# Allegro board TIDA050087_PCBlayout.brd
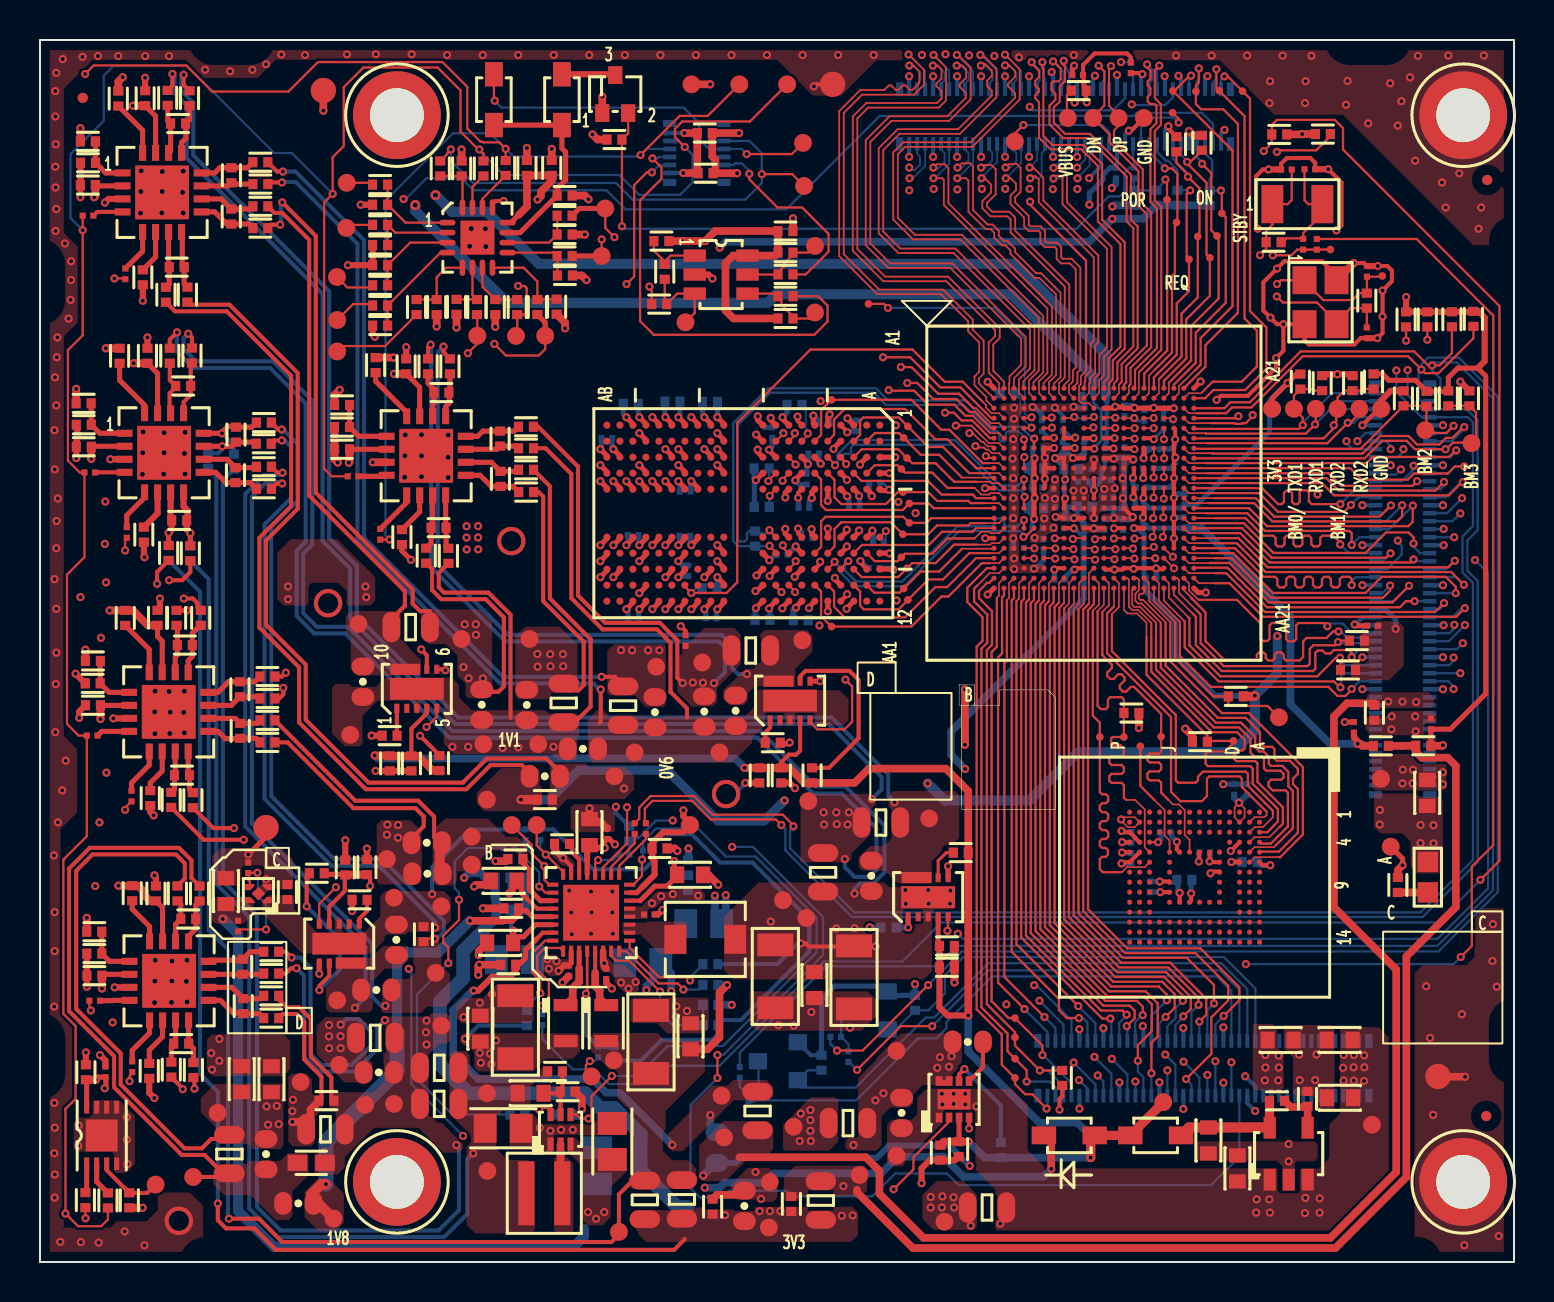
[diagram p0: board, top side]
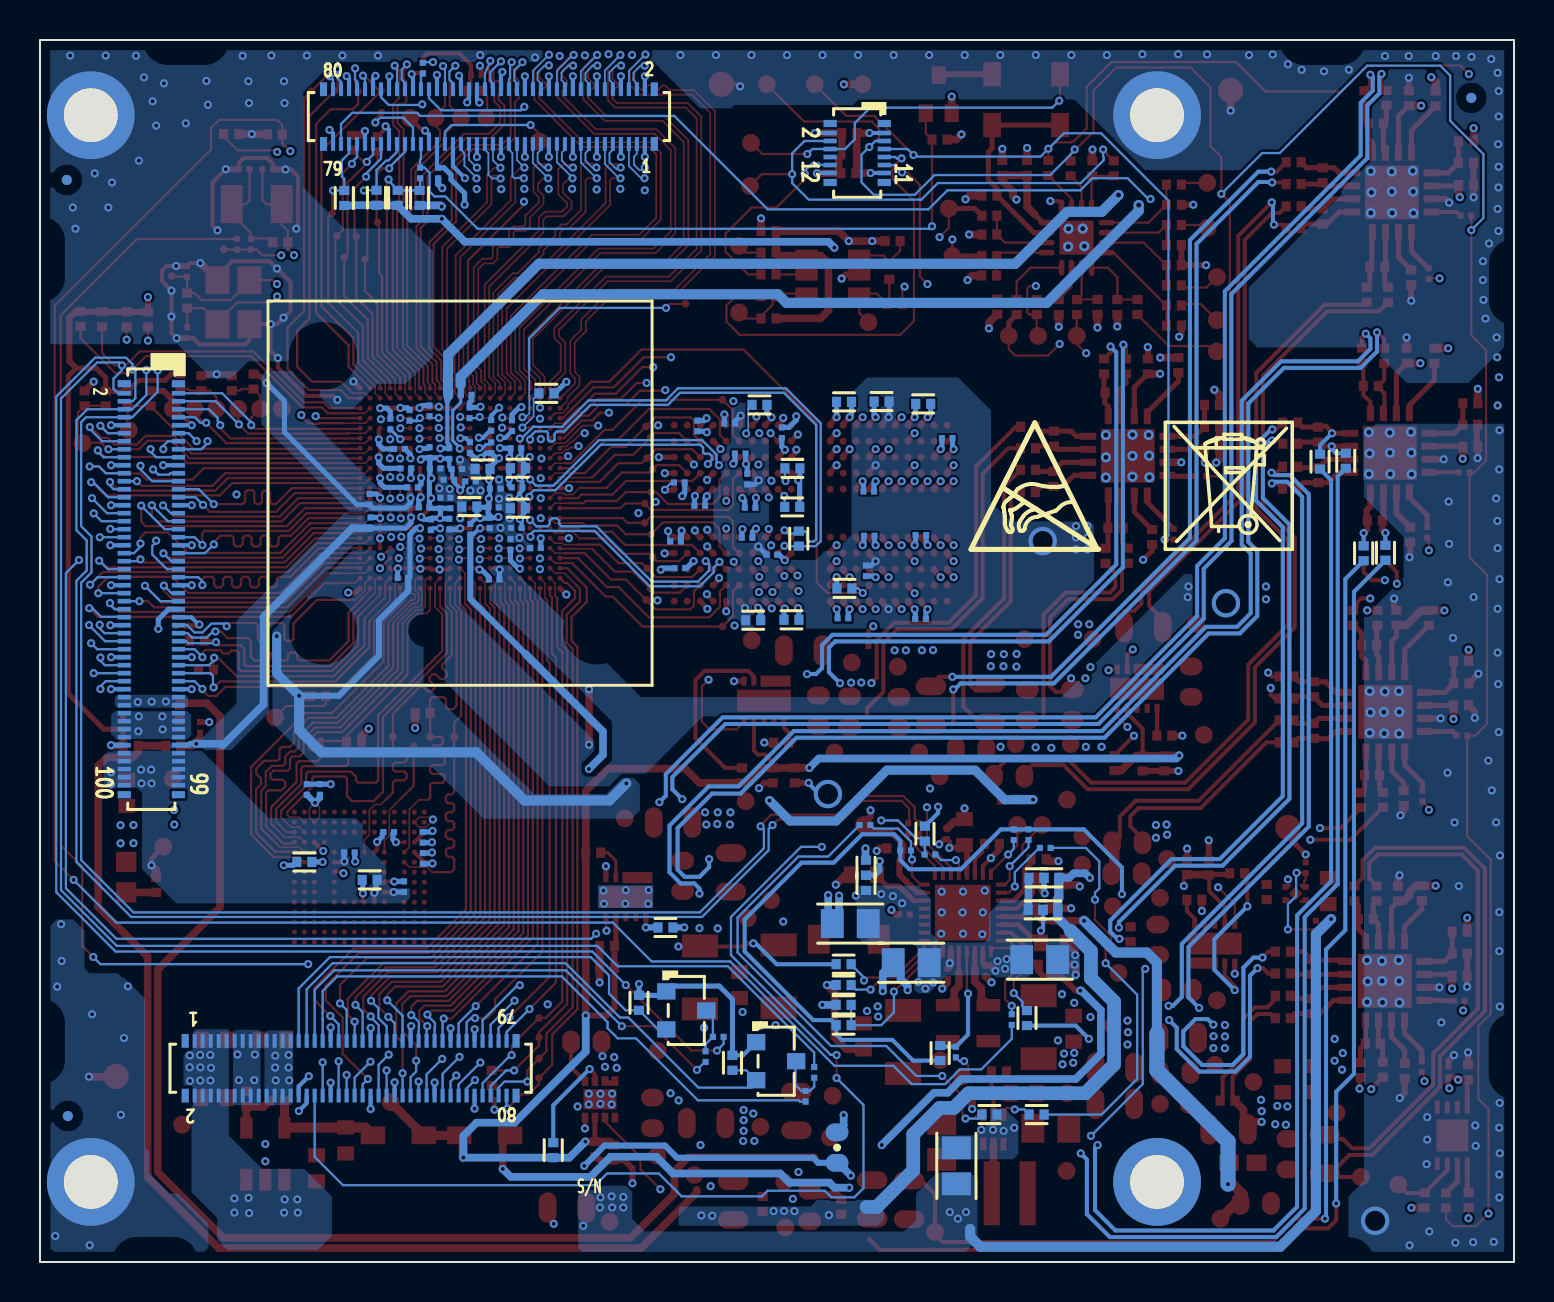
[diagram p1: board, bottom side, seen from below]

Outline 73.74 x 61.11 mm; copper layers: TOP, L2_GND_1, L3_INT_1, L4_PWR, L5_GND_2, BOTTOM. Coordinates in mm from the lower left corner of the outline.
Outline path: rectangle 0,0 73.74,61.11

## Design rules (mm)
constraint set DEFAULT: min track width 0.112, pair gap 0.127
net group DP1: nets I2C2_SCL I2C2_SDA
net group @SCH-51943_B2_0411A.MCIMX93-SOM: nets ADC_IN0 ADC_IN1 ADC_IN2 ADC_IN3 CLKIN1 CLKIN2 CLKO01 CLKO02 CLKO03 CLKO04 CSI_CLK_N CSI_CLK_P CSI_D0_N CSI_D0_P CSI_D1_N CSI_D1_P DRAM_CA0_A DRAM_CA1_A DRAM_CA2_A DRAM_CA3_A DRAM_CA4_A DRAM_CA5_A DRAM_CK_C_A DRAM_CK_T_A DRAM_CKE0_A DRAM_CKE1_A DRAM_DATA0_A DRAM_DATA1_A DRAM_DATA2_A DRAM_DATA3_A DRAM_DATA4_A DRAM_DATA5_A DRAM_DATA6_A DRAM_DATA7_A DRAM_DATA8_A DRAM_DATA9_A DRAM_DATA10_A DRAM_DATA11_A DRAM_DATA12_A DRAM_DATA13_A DRAM_DATA14_A DRAM_DATA15_A DRAM_DMI0_A DRAM_DMI1_A DRAM_NCS0_A DRAM_NCS1_A DRAM_NRESET DRAM_SDQS0_C_A DRAM_SDQS0_T_A DRAM_SDQS1_C_A DRAM_SDQS1_T_A DRAM_ZN DRAM_ZQ0 DSI_CLK_N DSI_CLK_P DSI_D0_N DSI_D0_P DSI_D1_N DSI_D1_P DSI_D2_N DSI_D2_P DSI_D3_N DSI_D3_P EMMC_VDDIM ENET1_MDC ENET1_MDIO ENET1_RD0 ENET1_RD1 ENET1_RD2 ENET1_RD3 ENET1_RX_CTL ENET1_RXC ENET1_TD0 ENET1_TD1 ENET1_TD2 ENET1_TD3 ENET1_TX_CTL ENET1_TXC ENET2_MDC ENET2_MDIO ENET2_RD0 ENET2_RD1 ENET2_RD2 ENET2_RD3 ENET2_RX_CTL ENET2_RXC ENET2_TD0 ENET2_TD1 ENET2_TD2 ENET2_TD3 ENET2_TX_CTL ENET2_TXC FSC_CTRL_H1 FSC_CTRL_H2 FSC_CTRL_H3 FSC_CTRL_H4 FSC_CTRL_H5 FSC_CTRL_L1 FSC_CTRL_L2 FSC_CTRL_L3 FSC_CTRL_L4 FSC_CTRL_L5 FT_EECLK FT_EECS FT_EEDATA FT_IO_NINT FT_IO_NRST FT_IOEXP1_SCL FT_IOEXP1_SDA FT_SCL FT_SDA GPIO_IO00 GPIO_IO01 GPIO_IO02 GPIO_IO03 GPIO_IO04 GPIO_IO05 GPIO_IO06 GPIO_IO07 GPIO_IO08 GPIO_IO09 GPIO_IO10 GPIO_IO11 GPIO_IO12 GPIO_IO13 GPIO_IO14 GPIO_IO15 GPIO_IO16 GPIO_IO17 GPIO_IO18 GPIO_IO19 GPIO_IO20 GPIO_IO21 GPIO_IO22 GPIO_IO23 GPIO_IO24 GPIO_IO25 GPIO_IO26 GPIO_IO27 GPIO_IO28 GPIO_IO29 I2C1_SCL I2C1_SDA JTAG_TCK JTAG_TDI JTAG_TDO JTAG_TMS LPD4/X_VDD1 LPD4/X_VDD2 LPD4/X_VDDQ LPD4/X_VDDQ_0V6 LVDS_CLK_N LVDS_CLK_P LVDS_TX0_N LVDS_TX0_P LVDS_TX1_N LVDS_TX1_P LVDS_TX2_N LVDS_TX2_P LVDS_TX3_N LVDS_TX3_P M1_SCL M1_SDA M2_SCL M2_SDA M3_SCL M3_SDA M4_SCL M5_SCL M5_SDA MX_POR_B N113524078 N113540349 N113540351 N113540485 N113540576 N113540646 N113540680 N113540755 N113540996 N113787187 N113787601 N113787940 N113791010 N113791044 N113791152 N113791186 N113791216 N113791250 N113798682 N113798752 N113798791 N113798839 N113798887 N113798893 N113798925 N113798968 N113799011 N113799045 N113816310 N113816380 N113816419 N113816455 N113816503 N113816509 N113816541 N113816573 N113819379 N113819449 N113819488 N113819524 N113819572 N113819642 N113819644 N113819688 N113819696 N113819730 N113821648 N113821718 N113821847 N113821913 N113821965 N113821999 N114152142 N114616846 N114789657 N114789678 N114814991 N114815134 N115328449 N115328489 N115328624 N115328664 N115344996 N115345040 N115345198 N115345238 N115885549 N115885630 N115909883 N115909890 N115909893 N115909896 N115909899 N115939435 N115991020 N115999748 N116014384 N116041401 N116083878 N116107496 N116113800 N116121400 N116137130 N116675602 N116676339 N116698763 N116700633 N116701055 N116701070 NVCC_1P8 NVCC_3P3 NVCC_AON NVCC_BBSM_1P8 NVCC_GPIO ODT_CA_A ONOFF PDM_CLK PDM_DATA0 PDM_DATA1 PMIC_32K_OUT PMIC_NINT PMIC_ON_REQ PMIC_SCLH PMIC_SCLL PMIC_SDAH PMIC_SDAL PMIC_STBY_REQ POR_B S1_CPU_VDD2_DDR S1_CPU_VDDQ_DDR S1_NVCC_BBSM_1V8 SAI1_RXD0 SAI1_TXC SAI1_TXD0 SAI1_TXFS SD1_CLK SD1_CMD SD1_DATA0 SD1_DATA1 SD1_DATA2 SD1_DATA3 SD1_DATA4 SD1_DATA5 SD1_DATA6 SD1_DATA7 SD1_STROBE SD2_CLK SD2_CMD SD2_DATA0 SD2_DATA1 SD2_DATA2 SD2_DATA3 SD2_NCD SD2_VSEL SD3_CLK SD3_CMD SD3_DATA0 SD3_DATA1 SD3_DATA2 SD3_DATA3 SYS_NRST TAMPER0 TAMPER1 TEMP_NINT UART1_RXD UART1_TXD UART2_RXD UART2_TXD USB1_DN USB1_DP USB1_ID USB1_RXN USB1_RXP USB1_TXN USB1_TXP USB1_VBUS USB1_VBUS_3V3 USB2_DN USB2_DP USB2_ID USB2_VBUS_3V3 VBUS1_DET_3V3 VBUS2_DET_3V3 VDD2_DDR VDD_ANA_0P8 VDD_ANA_0V8 VDD_ANA_1P8 VDD_ANA_1V8 VDD_SNVS_0V8 VDD_SOC VDD_USB_3P3 VDDQ_DDR VLS_3V3 VMEAS_3V3 WDOG_B XTALI_24M XTALI_32K XTALO_24M XTALO_32K

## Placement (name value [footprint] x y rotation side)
BH801  106MILS  [MH_CIR173D106T_CUST]  71.2 57.35 0 top
BH802  106MILS  [MH_CIR173D106T_CUST]  17.86 57.35 0 top
BH803  106MILS  [MH_CIR173D106T_CUST]  17.86 4.01 0 top
BH804  106MILS  [MH_CIR173D106T_CUST]  71.2 4.01 0 top
C101  1uF  [0201]  53.26 40.43 270 bottom
C102  0.22uF  [0201]  54.25 40.48 270 bottom
C106  1uF  [0201]  53.28 39.12 180 bottom
C107  1uF  [0201]  53.7 37.95 270 bottom
C108  10uF  [0402]  52.26 37.78 180 bottom
C109  1uF  [0201]  52.2 39.04 0 bottom
C110  1uF  [0201]  53.97 39.68 0 bottom
C111  1uF  [0201]  52.88 39.65 0 bottom
C114  1uF  [0201]  53.21 37.96 270 bottom
C116  1uF  [0201]  51.02 34.13 0 bottom
C117  1uF  [0201]  53.26 36.9 90 bottom
C118  1uF  [0201]  57.2 36.97 90 bottom
C119  1uF  [0201]  57.25 38.14 90 bottom
C124  10uF  [0402]  51.6 39.66 180 bottom
C129  1uF  [0201]  55.58 34.21 0 bottom
C130  1uF  [0201]  55.43 39.69 0 bottom
C131  1uF  [0201]  54.19 36.87 90 bottom
C132  1uF  [0201]  51.17 40.72 270 bottom
C134  1uF  [0201]  52.23 40.73 270 bottom
C135  1uF  [0201]  55.1 38.74 0 bottom
C136  10uF  [0402]  49.83 37.7 180 bottom
C137  1uF  [0201]  51.24 36.96 90 bottom
C138  1uF  [0201]  51.05 37.74 0 bottom
C139  1uF  [0201]  49.91 36.71 180 bottom
C140  1uF  [0201]  50.96 38.67 0 bottom
C141  1uF  [0201]  50.2 35.89 270 bottom
C142  22uF  [0603]  11.58 9.14 90 top
C143  22uF  [0603]  10.09 9.15 90 top
C144  1uF  [0201]  50.12 41.82 90 bottom
C145  1uF  [0201]  54.52 37.74 180 bottom
C146  1uF  [0201]  52.21 36.64 90 bottom
C147  1uF  [0201]  51.17 41.84 90 bottom
C148  1uF  [0201]  55.75 40.66 0 bottom
C149  1uF  [0201]  56.21 41.9 90 bottom
C151  10uF  [0402]  49.83 39.69 180 bottom
C152  1uF  [0201]  49.93 40.69 180 bottom
C153  1uF  [0201]  32.29 31.08 90 top
C154  1uF  [0201]  49.87 38.74 180 bottom
C155  1uF  [0201]  52.42 43.37 180 bottom
C156  1uF  [0201]  48.95 35.7 180 bottom
C201  10uF  [0402]  31.64 43.03 0 bottom
C202  10uF  [0402]  38.06 32.09 180 bottom
C203  1uF  [0201]  37.13 35.37 180 bottom
C204  1uF  [0201]  39.24 41.93 0 bottom
C205  1uF  [0201]  38.36 39.15 90 bottom
C206  10uF  [0402]  36.15 32.11 0 bottom
C207  10uF  [0402]  33.52 43.01 180 bottom
C208  1uF  [0201]  38.36 36.22 180 bottom
C209  1uF  [0201]  32.42 34.57 270 bottom
C210  1uF  [0201]  32.28 38.53 180 bottom
C211  1uF  [0201]  36.63 41.47 270 bottom
C212  1uF  [0201]  33.57 32.19 180 bottom
C213  1uF  [0201]  32.25 36.32 180 bottom
C214  1uF  [0201]  38.21 37.72 180 bottom
C215  10uF  [0402]  29.55 42.91 180 bottom
C216  1uF  [0201]  40.86 41.81 90 bottom
C217  1uF  [0201]  40.73 37.82 0 bottom
C218  1uF  [0201]  41.73 34.7 0 bottom
C219  1uF  [0201]  28.35 41.2 180 bottom
C220  1uF  [0201]  29.67 36.35 180 bottom
C221  1uF  [0201]  38.71 40.43 180 bottom
C222  1uF  [0201]  29.69 32.15 180 bottom
C401  18pF  [0201]  63.52 54.65 0 top
C402  18pF  [0201]  62.35 54.63 180 top
C403  12pF  [0201]  66.38 49.54 90 top
C404  12pF  [0201]  66.37 46.47 270 top
C405  0.1uF  [0402]  54.75 53.21 270 bottom
C501  4.7uF  [0402]  57.24 19.11 0 bottom
C502  0.22uF  [0201]  58.26 20.48 180 bottom
C503  0.22uF  [0201]  55.52 18.77 90 bottom
C504  10uF  [0402]  60.51 20.01 0 bottom
C505  0.22uF  [0201]  54.6 21.24 270 bottom
C506  0.22uF  [0201]  54.59 20.18 270 bottom
C507  0.22uF  [0201]  56.29 21.5 0 bottom
C508  0.22uF  [0201]  59.74 23.63 90 bottom
C509  1uF  [0201]  60.39 23.63 90 bottom
C702  4.7uF  [0805]  33.2 16.92 180 bottom
C704  2.2uF  [0603]  27.49 21.5 270 top
C706  2.2uF  [0402]  26.12 20.91 0 top
C707  47uF  [1206_T_A1]  36.79 14.28 270 top
C708  10uF  [0603]  38.74 13.85 270 top
C709  0.1uF  [0201]  30.49 17.38 0 top
C712  4.7uF  [0805]  30.16 14.97 180 bottom
C713  0.1uF  [0201]  28.33 14.41 270 top
C714  47uF  [1206_T_A1]  30.56 11.01 90 top
C715  10uF  [0603]  32.54 11.28 270 top
C718  4.7uF  [0805]  28.63 6.03 90 top
C719  120pF  [0603]  24.54 8.44 0 top
C720  22uF  [0805]  23.17 6.69 0 top
C721  4.7uF  [0805]  23.73 15.12 0 bottom
C722  47uF  [1206_T_A1]  23.78 11.74 270 top
C723  10uF  [0603]  22.03 11.67 270 top
C724  4.7uF  [0603]  23.02 15.96 0 top
C725  2.2uF  [0402]  23.42 14.87 180 top
C726  2.2uF  [0603]  9.3 18.55 90 top
C727  2.2uF  [0402]  12.38 18.5 90 top
C729  2.2uF  [0402]  23.58 17.69 180 top
C730  2.2uF  [0402]  23.78 20.15 180 top
C731  2.2uF  [0402]  30.99 20.68 0 top
C801  10uF  [0603]  65.01 11.1 180 top
C802  10uF  [0603]  65.03 8.21 180 top
C803  22uF  [0603]  69.4 23.46 270 top
C804  1uF  [0201]  69.58 26.91 90 top
C805  22uF  [0603]  62.06 11.1 0 top
C806  1uF  [0201]  65.73 26.73 90 top
C807  4.7uF  [0402]  66.75 27.47 270 top
C808  1uF  [0201]  66.66 31.82 180 top
C809  1uF  [0201]  53.82 54.45 270 bottom
C901  1uF  [0402]  45.95 5.65 270 top
C902  0.01uF  [0402]  9.81 41.37 90 top
C903  1uF  [0402]  5.38 45.32 90 top
C904  0.1uF  [0402]  2.19 40.77 180 top
C905  0.01uF  [0402]  7.42 17.15 180 top
C906  0.1uF  [0402]  45.04 5.47 270 top
C907  0.01uF  [0402]  6.96 37.08 180 top
C908  0.01uF  [0402]  9.78 39.35 270 top
C909  1uF  [0402]  15.27 19.73 90 top
C910  0.01uF  [0402]  9.58 54.34 90 top
C911  1uF  [0402]  5.26 58.2 90 top
C912  0.1uF  [0402]  16.35 19.74 90 top
C913  0.1uF  [0402]  2.4 53.85 180 top
C914  10uF  [0603]  58.45 6.08 270 top
C915  4.7uF  [0402]  33.3 54.45 0 top
C916  0.1uF  [0402]  33.26 56.45 0 top
C917  0.01uF  [0402]  6.91 56.93 180 top
C918  2.2uF  [0603]  59.9 4.68 90 top
C920  0.01uF  [0402]  6.84 49.75 180 top
C921  0.01uF  [0402]  9.57 52.28 270 top
C922  1uF  [0402]  45.37 15.81 0 top
C923  0.1uF  [0402]  45.37 14.74 0 top
C924  0.01uF  [0402]  23.01 41.17 90 top
C925  1uF  [0402]  15.11 40.64 180 top
C926  0.1uF  [0402]  18.32 44.79 90 top
C927  0.01uF  [0402]  20.08 43.48 180 top
C928  1uF  [0402]  25.6 54.71 90 top
C929  0.1uF  [0402]  24.36 54.71 90 top
C930  1uF  [0402]  17.49 24.93 270 top
C931  0.1uF  [0402]  18.58 24.93 270 top
C932  0.01uF  [0402]  19.94 36.72 180 top
C933  0.01uF  [0402]  7.06 10.92 180 top
C934  1uF  [0402]  5.88 32.22 90 top
C935  0.1uF  [0402]  37.08 24.33 270 top
C936  0.01uF  [0402]  10 28.64 90 top
C937  0.1uF  [0402]  2.65 27.84 180 top
C938  1uF  [0402]  35.98 24.33 270 top
C939  0.01uF  [0402]  7.25 30.85 180 top
C940  0.01uF  [0402]  7.1 24.35 180 top
C941  0.01uF  [0402]  10.01 26.56 270 top
C942  0.1uF  [0402]  37.29 51.55 0 top
C943  1uF  [0402]  2.3 9.49 90 top
C944  0.22uF  [0201]  3.28 9.51 90 top
C945  0.01uF  [0402]  10.14 14.76 90 top
C946  1uF  [0402]  5.8 18.43 90 top
C947  0.1uF  [0402]  2.72 14.32 180 top
C948  0.01uF  [0402]  7.16 43.81 180 top
C949  0.01uF  [0402]  23.03 39.16 270 top
C950  0.01uF  [0402]  10.17 12.79 270 top
C951  220pF  [0402]  15.99 18.11 180 top
C952  220pF  [0402]  42.45 16.73 180 bottom
C953  220pF  [0402]  17.49 26.32 180 top
C954  220pF  [0402]  36.66 25.97 0 top
C996  2.2uF  [0603]  23.2 19.06 0 top
C1013  2.2uF  [0603]  32.52 19.36 180 top
C1021  0.1uF  [0201]  26.45 14.56 270 top
C1022  0.1uF  [0201]  28.38 21.42 90 top
C1023  47uF  [0805]  27.9 4.81 90 bottom
C1024  47uF  [1206_T_A1]  40.72 14.23 270 top
D601  G  [LED-0603_L_A1]  69.42 19.25 270 top
D901  PMEG2010EJ  [DIO_SOD323F_B_A1]  55.81 6.33 90 top
D902  PMEG2010EJ  [DIO_SOD323F_B_A1]  51.49 6.33 270 top
D903  PMEG2010EJ  [DIO_SOD323F_B_A1]  22.71 58.12 0 top
D904  PMEG2010EJ  [DIO_SOD323F_B_A1]  26.11 58.12 0 top
J801  CON_B2B_2X40  [CON_B2B_2X40M_0P4_SM_ST_D_A1]  58.2 9.69 0 bottom
J802  CON_B2B_2X40  [CON_B2B_2X40M_0P4_SM_ST_D_A1]  51.28 57.28 180 bottom
J803  CON_B2B_2X50  [CON_B2B_2X50M_0P4_SM_ST_A_A2]  68.17 33.64 270 bottom
J901  CON_B2B_2X6  [CON_B2B_2X6M_0P4_SM_ST_A2]  32.86 55.46 270 bottom
L102  1K  [FBEAD-0603_A_A1]  13.57 4.96 180 top
L702  0.47uH  [IND2_3_3P5X3P2_B_A1]  33.28 16.14 0 top
L704  0.47uH  [IND2_1P8_2X1P2_POL_A1]  28.33 11.95 270 top
L705  1uH  [IND2_1P8_3P2X3P5_A_A1]  25.23 3.44 180 top
L706  0.47uH  [IND2_1P8_2X1P2_POL_A1]  26.29 11.95 270 top
NOREF  -  []  24.49 14.95 0 top
NOREF#2  -  []  67.98 -0.99 0 top
NOREF#3  -  []  -73.52 -8.72 0 top
NOREF#4  -  []  9.15 -1.01 0 top
NOREF#5  -  []  24.73 14.5 90 top
NOREF#6  -  []  26.84 6.04 90 top
NOREF#7  -  []  22.98 10.14 0 top
NOREF#8  -  []  51.26 13.49 0 top
NOREF#9  -  []  35.03 14.54 90 top
NOREF#10  -  []  74.73 11.03 90 top
NOREF#11  -  []  31.26 5.03 90 top
NOREF#12  -  []  22.27 6.69 0 top
NOREF#13  -  []  35.98 12.68 90 top
NOREF#14  -  []  85.31 62.11 0 top
NOREF#15  -  []  32.2 16.3 90 top
NOREF#16  -  []  27.73 10.95 90 top
NOREF#17  -  []  -82.56 -20.2 0 top
NOREF#18  -  []  24.17 6.06 90 top
NOREF#19  -  []  54.51 15.99 0 top
NOREF#20  -  []  7.04 -214.61 0 top
NOREF#21  -  []  37.91 9.09 90 top
NOREF#22  -  []  7.67 63.11 0 top
NOREF#23  -  [unnamed#2]  72.35 7.3 0 top
NOREF#24  -  []  61.51 4.12 90 top
NOREF#25  -  []  34.21 56.06 90 top
NOREF#26  -  []  0.01 50.91 0 top
NOREF#27  -  []  66.81 37.04 90 top
NOREF#28  -  []  142.16 62.11 0 top
NOREF#29  -  []  -7 -7 0 top
NOREF#30  -  []  68.69 139.96 0 top
NOREF#31  -  []  0 60.35 0 top
NOREF#32  -  []  22.17 6.06 0 top
NOREF#33  -  []  74.74 113.25 90 top
NOREF#34  -  []  53.2 91.04 0 top
NOREF#35  -  []  22.98 10.14 90 top
NOREF#36  -  []  -0.98 73.4 270 top
NOREF#37  -  []  25.69 12.95 90 top
NOREF#38  -  []  44.73 9.14 0 top
NOREF#39  -  []  33.78 51.65 90 top
NOREF#40  -  []  23.78 10.17 90 top
NOREF#41  -  []  19.86 5.3 0 top
NOREF#42  -  []  32.3 16.92 0 top
NOREF#43  -  []  40.72 12.66 90 top
NOREF#44  -  []  25.57 15.47 0 top
NOREF#45  -  []  10.43 17.92 90 top
NOREF#46  -  [unnamed#2]  72.4 54.11 0 top
NOREF#47  -  []  61.51 4.12 0 top
NOREF#48  -  []  42.06 14.03 90 top
NOREF#49  -  []  150.47 11.03 90 top
NOREF#50  -  []  28.33 11.05 90 top
NOREF#51  -  []  61.51 4.12 0 top
NOREF#52  -  []  10.43 18.92 0 top
NOREF#53  -  []  30.03 5.19 90 top
NOREF#54  -  []  36.79 12.71 90 top
NOREF#55  -  []  25.54 5.9 0 top
NOREF#56  -  []  10.5 18.1 90 top
NOREF#57  -  []  27.9 3.91 90 top
NOREF#58  -  []  150.47 50.15 90 top
NOREF#59  -  []  0.22 50.03 0 top
NOREF#60  -  []  25.65 18.87 0 top
NOREF#61  -  []  29.76 12.61 0 top
NOREF#62  -  []  9.58 62.11 0 top
NOREF#63  -  []  -0.98 10.29 270 top
NOREF#64  -  []  37.91 9.09 90 top
NOREF#65  -  []  25.24 6.04 0 top
NOREF#66  -  []  31.36 9.41 90 top
NOREF#67  -  []  -82.57 -20.2 0 top
NOREF#68  -  []  19.86 58.65 0 top
NOREF#69  -  []  42.41 11.63 90 top
NOREF#70  -  []  61.01 4.62 90 top
NOREF#71  -  []  40.76 16.93 0 top
NOREF#72  -  []  31.78 16.14 0 top
NOREF#73  -  []  64.66 -216.52 0 top
NOREF#74  -  []  45.98 9.05 0 top
NOREF#75  -  []  25.57 15.47 90 top
NOREF#76  -  []  51.26 13.49 90 top
NOREF#77  -  []  22.73 15.75 90 top
NOREF#78  -  []  73.2 5.3 0 top
NOREF#79  -  []  28.63 5.13 90 top
NOREF#80  -  []  26.29 11.05 90 top
NOREF#81  -  []  84.89 -1.01 0 top
NOREF#82  -  []  -7 131.22 0 top
NOREF#83  -  []  66.81 43.44 90 top
NOREF#84  -  []  8.55 63.32 0 top
NOREF#85  -  []  46.73 7.14 90 top
NOREF#86  -  []  27.27 3.81 0 top
NOREF#87  -  []  36.26 14.39 0 top
NOREF#88  -  []  35.98 12.68 0 top
NOREF#89  -  []  149.31 129.09 0 top
NOREF#90  -  []  0.01 48.1 90 top
NOREF#91  -  []  26.54 5.9 90 top
NOREF#92  -  []  29.26 5.03 0 top
NOREF#93  -  []  33.78 53.5 0 top
NOREF#94  -  []  29.27 3.81 90 top
NOREF#95  -  []  47.57 44.4 0 top
NOREF#96  -  []  129.45 99.54 0 top
NOREF#97  -  []  46.48 7.23 90 top
NOREF#98  -  []  31.16 12.34 90 top
NOREF#99  -  []  66.43 62.11 0 top
NOREF#100  -  []  27.73 10.95 0 top
NOREF#101  -  []  26.83 5.19 0 top
NOREF#102  -  []  66.95 0.22 0 top
NOREF#103  -  []  155.14 127.62 0 top
NOREF#104  -  []  32.2 16.3 0 top
NOREF#105  -  []  7.09 -218.42 0 top
NOREF#106  -  []  30.56 9.43 90 top
NOREF#107  -  []  9.58 63.11 0 top
NOREF#108  -  []  34.21 56.46 90 top
NOREF#109  -  []  69.52 23.84 90 top
NOREF#110  -  []  22.83 15.12 0 top
NOREF#111  -  []  69.52 23.37 90 top
NOREF#112  -  []  25.54 7.38 0 top
NOREF#113  -  []  -7 -7 90 top
NOREF#114  -  []  536.26 -201.11 0 top
NOREF#115  -  []  174.34 17.02 0 top
NOREF#116  -  []  31.53 14.54 0 top
NOREF#117  -  []  61.01 4.62 0 top
NOREF#118  -  []  0.23 -0.14 90 top
NOREF#119  -  []  67.98 0.01 0 top
NOREF#120  -  []  143.71 -0.99 0 top
NOREF#121  -  []  39.92 12.63 0 top
NOREF#122  -  []  39.92 12.63 90 top
NOREF#123  -  [unnamed#2]  2.14 58.21 0 top
NOREF#124  -  []  59.51 22.49 0 top
NOREF#125  -  []  85.31 125.22 0 top
NOREF#126  -  []  -52.18 81.92 0 top
NOREF#127  -  []  29.5 16.07 90 top
NOREF#128  -  []  -56.16 37.8 0 top
NOREF#129  -  []  -0.99 112.11 270 top
NOREF#130  -  []  15.32 1.47 0 top
NOREF#131  -  []  9.58 125.22 0 top
NOREF#132  -  []  24.33 3.44 0 top
NOREF#133  -  []  42.41 11.63 90 top
NOREF#134  -  []  10.5 18.75 0 top
NOREF#135  -  []  74.73 74.14 90 top
NOREF#136  -  []  150.47 74.14 90 top
NOREF#137  -  []  29.26 14.97 0 top
NOREF#138  -  []  74.74 50.15 90 top
NOREF#139  -  []  66.81 23.37 0 top
NOREF#140  -  []  73.2 58.64 0 top
NOREF#141  -  []  -27.17 -204.83 0 top
NOREF#142  -  []  142.16 125.22 0 top
NOREF#143  -  []  -0.99 49 270 top
NOREF#144  -  []  31.16 12.34 90 top
NOREF#145  -  []  47.57 42.55 90 top
NOREF#146  -  []  66.07 0.01 0 top
NOREF#147  -  []  37.56 11.49 90 top
NOREF#148  -  []  31.5 53.98 0 top
NOREF#149  -  []  150.47 113.25 90 top
NOREF#150  -  []  54.51 15.99 90 top
NOREF#151  -  []  66.43 125.22 0 top
NOREF#152  -  [unnamed#2]  2.14 58.21 180 bottom
NOREF#153  -  []  27.15 35.64 180 bottom
NOREF#154  -  []  17.44 35.64 180 bottom
NOREF#155  -  []  24.74 19.8 180 bottom
NOREF#156  -  [unnamed#2]  72.35 7.3 180 bottom
NOREF#157  -  []  65.98 49.62 180 bottom
NOREF#158  -  [unnamed#2]  72.4 54.11 180 bottom
Q901  NX3008NBKW  [SOT323-3L_1P3_2X1P25_A2]  28.78 58.4 0 top
Q902  BSS138-7-F  [SOT23-3L_1P9_2P9X1P3_A1]  36.91 10.04 270 bottom
Q903  BSS138-7-F  [SOT23-3L_1P9_2P9X1P3_A1]  41.41 12.58 270 bottom
QZ401  32.768KHz  [XTAL2_2P5_3P2X1P5]  62.9 52.9 0 top
R101  0E  [0402]  19.18 16.39 270 top
R102  0E  [RC0805]  39.17 19.49 90 top
R103  0E  [RC0603]  19.38 19.42 180 top
R104  0E  [RC0603]  11.31 5.39 90 top
R105  0E  [0402]  33.65 2.77 90 top
R106  0E  [0402]  14.33 8.07 0 top
R107  0E  [0402]  37.59 2.9 270 top
R108  0E  [0402]  25.25 23.12 0 top
R109  0E  [RC0603]  22.1 27.87 270 top
R110  0E  [RC0603]  33.23 27.53 270 top
R111  0E  [RC0603]  12.92 2.93 180 top
R112  0E  [0402]  69.19 25.82 180 top
R113  0E  [0402]  67.08 25.81 0 top
R201  10K  [0402]  33.5 33.69 0 bottom
R202  0E  [RC0603]  16.95 9.48 180 top
R203  0E  [RC0603]  24.35 27.86 90 top
R204  120E  [0402]  48.4 43.44 180 bottom
R205  150E  [0402]  35.78 36.17 270 bottom
R206  0E  [RC0603]  30.77 27.49 90 top
R207  10K  [0402]  36.1 39.69 0 bottom
R208  10K  [0402]  36.11 37.76 0 bottom
R209  240E  [0201]  41.76 38.98 0 bottom
R210  0E  [0402]  37.74 42.86 0 bottom
R211  240E  [0201]  41.94 36.04 0 bottom
R301  0E  [0201]  51.91 59.35 0 top
R302  200E  [0201]  52.25 42.47 270 bottom
R303  200E  [0201]  54.25 42.56 90 bottom
R304  0E  [0201]  54.59 59.7 270 bottom
R305  200E  [0201]  55.25 42.34 90 bottom
R306  4.7K  [0402]  70.63 47.14 270 top
R307  4.7K  [0402]  71.71 47.16 270 top
R308  4.7K  [0402]  69.4 47.14 270 top
R309  4.7K  [0402]  68.34 47.14 270 top
R310  10K  [0402]  65.43 29.61 180 top
R311  10K  [0402]  65.88 31.07 180 top
R312  4.7K  [0402]  59.82 28.29 180 top
R401  100K  [0402]  56.9 53.22 90 bottom
R403  10K  [0402]  51.14 9.2 270 top
R404  100K  [0402]  55.84 53.21 90 bottom
R405  100K  [0402]  58.51 53.21 90 bottom
R406  0E  [0201]  54.72 54.46 270 bottom
R411  0E  [0201]  63.87 50.89 270 top
R412  0E  [0201]  63.19 50.89 90 top
R413  4.7M  [0402]  61.71 51 180 top
R414  510K  [0402]  66.37 48.07 270 top
R415  100K  [0402]  56.85 55.9 90 top
R416  100K  [0402]  58.13 55.97 90 top
R417  100K  [0402]  64.18 56.4 180 top
R418  100K  [0402]  61.99 56.39 0 top
R501  10K  [0402]  58.02 26.02 0 top
R502  10K  [0402]  54.6 27.45 180 top
R601  4.7K  [0402]  63.05 44.03 270 top
R602  10K  [0402]  66.71 44.03 270 top
R603  4.7K  [0402]  69.36 43.17 270 top
R604  4.7K  [0402]  70.45 43.19 270 top
R605  1K  [0402]  67.93 18.86 270 top
R609  100K  [0402]  64.14 43.95 90 top
R610  100K  [0402]  65.66 43.95 90 top
R611  100K  [0402]  68.2 43.19 90 top
R612  100K  [0402]  71.51 43.19 90 top
R613  30K  [0402]  51.96 58.58 0 top
R614  52.3K  [0201]  54.57 59.72 270 top
R702  0E  [RC0603]  27.16 25.66 0 top
R703  100K  [0402]  28.71 10.45 90 bottom
R706  0E  [0201]  27.92 10.5 270 bottom
R707  0E  [0201]  25.13 12.12 90 bottom
R712  4.7K  [0402]  43.77 12.96 270 bottom
R713  4.7K  [0402]  39.1 9.96 270 bottom
R714  0E  [0201]  29.75 21.67 90 top
R715  0E  [0201]  30.31 21.67 90 top
R717  0E  [0201]  39.81 11.26 180 bottom
R719  0E  [0201]  35.01 9.48 90 bottom
R724  0E  [0201]  40.44 10.27 270 bottom
R725  0E  [0201]  35.44 8.29 270 bottom
R726  0E  [RC0805]  30.26 3.11 270 top
R727  0E  [RC0805]  19.97 9.71 180 top
R801  0E  [RC0603]  33.86 5.72 270 bottom
R802  0E  [RC0805]  47.38 2.73 0 top
R901  400mE  [RC0603]  43.1 7.46 90 top
R902  0E  [0402]  11.19 40.92 180 top
R903  0E  [0402]  11.2 41.98 180 top
R904  20mE  [RC0805]  40.42 6.95 180 top
R905  0E  [0402]  7.98 18.43 270 top
R906  0E  [0201]  2.49 39.48 180 top
R907  10K  [0402]  48.06 5.6 270 bottom
R908  1K  [RC0603]  46.41 11.01 359.8 top
R909  0E  [0402]  6.88 18.43 270 top
R910  0E  [0201]  4.34 36.48 270 top
R911  0E  [0402]  7.52 35.44 90 top
R912  499E  [0402]  5.2 36.37 270 top
R913  10K  [0402]  2.19 41.87 180 top
R914  10K  [0402]  2.18 42.94 180 top
R915  10K  [0402]  3.98 45.32 90 top
R916  0E  [0402]  6.44 35.46 90 top
R917  0E  [0402]  11.2 39.77 180 top
R918  0E  [0402]  11.2 38.67 180 top
R919  499E  [RC0603]  17.83 16.11 270 top
R920  10E  [RC0603]  16.83 13.6 0 top
R921  0E  [0402]  11.02 53.9 180 top
R922  10K  [0402]  13.85 19.44 0 top
R923  0E  [0402]  11.02 55 180 top
R924  0E  [0402]  7.48 58.2 270 top
R926  0E  [0201]  2.4 52.32 180 top
R927  0E  [0402]  6.39 58.21 270 top
R928  0E  [0201]  4.27 49.42 270 top
R929  0E  [0402]  7.38 48.37 90 top
R930  806E  [0402]  5.14 49.24 270 top
R931  1E  [RC0603]  41.59 19.31 90 top
R932  5mE  [RC0805]  42.07 21.98 180 top
R933  10K  [0402]  2.4 54.97 180 top
R934  10K  [0402]  2.4 56.04 180 top
R935  0E  [0402]  6.3 48.37 90 top
R936  10K  [0402]  3.92 58.18 90 top
R937  0E  [0402]  11.02 52.79 180 top
R938  10K  [0402]  46.06 20.47 0 top
R939  0E  [0402]  11.02 51.7 180 top
R941  0E  [0402]  24.31 40.69 180 top
R942  2E  [RC0603]  16.15 29.02 90 top
R943  0E  [0402]  24.31 41.77 180 top
R944  50mE  [RC0805]  18.54 31.75 0 top
R945  0E  [0402]  20.51 44.79 270 top
R946  0E  [0201]  15.66 39.29 180 top
R947  0E  [0402]  19.41 44.79 270 top
R948  0E  [0201]  17.02 36.39 270 top
R949  0E  [0402]  20.43 35.31 90 top
R950  1.27K  [0402]  18.11 36.25 270 top
R951  10K  [0402]  19.98 24.95 270 top
R952  10K  [0402]  26.24 53.33 180 top
R953  10K  [0402]  21.09 54.68 270 top
R955  10K  [0402]  15.11 41.75 180 top
R956  10K  [0402]  15.11 42.86 180 top
R957  0E  [0402]  7.68 9.6 90 top
R958  0E  [0402]  19.32 35.32 90 top
R959  10K  [0402]  16.79 44.85 90 top
R960  0E  [0402]  18.84 47.75 270 top
R961  0E  [0402]  20.02 54.68 270 top
R962  0E  [0402]  17.02 47.83 180 top
R963  0E  [0402]  17.02 48.84 180 top
R964  0E  [0402]  17.02 51.86 180 top
R965  0E  [0402]  23.29 54.71 270 top
R966  0E  [0402]  17.02 53.88 180 top
R967  0E  [0402]  6.57 9.62 90 top
R968  0E  [0402]  22.18 54.68 270 top
R969  0E  [0402]  21.86 47.75 270 top
R970  0E  [0402]  23.87 47.75 270 top
R971  10K  [0402]  28.74 56.13 0 top
R972  0E  [0402]  24.88 47.75 270 top
R973  2E  [RC0603]  34.8 27.57 90 top
R974  50mE  [RC0805]  35.56 30.58 180 top
R975  4.7K  [0402]  25.85 47.77 90 top
R976  4.7K  [0402]  22.78 47.75 90 top
R977  4.7K  [0402]  20.84 47.76 90 top
R978  4.7K  [0402]  17.02 52.87 180 top
R979  4.7K  [0402]  17.02 50.86 180 top
R980  4.7K  [0402]  17.02 49.85 180 top
R981  4.7K  [0402]  17.02 46.83 180 top
R982  4.7K  [0402]  19.84 47.75 270 top
R983  0E  [0402]  11.38 28.18 180 top
R984  0E  [0402]  11.38 29.28 180 top
R985  10K  [0402]  38.62 24.34 270 top
R987  0E  [0402]  8.04 32.22 270 top
R988  0E  [0201]  2.61 26.32 180 top
R989  0E  [0402]  6.83 32.21 270 top
R990  0E  [0201]  4.58 23.3 270 top
R991  0E  [0402]  7.65 23.1 90 top
R992  2.05K  [0402]  5.52 23.2 270 top
R993  10K  [0402]  2.64 28.94 180 top
R994  10K  [0402]  2.65 30.06 180 top
R995  10K  [0402]  4.27 32.21 90 top
R996  0E  [0402]  6.56 23.11 90 top
R997  0E  [0402]  11.38 27.09 180 top
R998  1E  [RC0603]  25.25 24.29 180 top
R999  400mE  [RC0603]  19.35 20.97 180 top
R1000  0E  [0402]  11.38 25.98 180 top
R1001  250mE  [RC0805]  9.47 5.4 90 top
R1002  4.99E  [RC0603]  35.24 2.8 90 top
R1003  100mE  [RC0805]  39.06 3.08 90 top
R1004  100mE  [RC0805]  14.28 6.64 180 top
R1005  0E  [0402]  11.57 14.43 180 top
R1006  0E  [0402]  11.57 15.52 180 top
R1007  250mE  [RC0805]  29.17 27.82 90 top
R1008  0E  [0402]  7.6 45.33 270 top
R1009  100K  [0402]  4.47 3.09 90 top
R1010  2.2K  [0402]  31.25 49.52 270 top
R1011  10K  [0402]  31.08 51.05 180 top
R1012  10K  [0402]  37.29 47.18 0 top
R1013  10K  [0402]  37.29 50.48 0 top
R1014  250mE  [RC0805]  16.77 11.21 180 top
R1015  0E  [0402]  30.98 47.9 180 top
R1016  0E  [0402]  37.29 48.29 0 top
R1017  100mE  [RC0805]  26.2 27.96 90 top
R1018  0E  [0402]  37.29 49.39 0 top
R1019  0E  [0201]  2.74 13.07 180 top
R1020  0E  [0402]  6.49 45.32 270 top
R1021  0E  [0201]  4.61 9.77 270 top
R1022  0E  [0402]  24.31 39.61 180 top
R1023  3.24K  [0402]  5.47 9.55 270 top
R1024  10K  [0402]  2.72 15.42 180 top
R1025  10K  [0402]  2.72 16.52 180 top
R1026  0E  [0402]  24.32 38.5 180 top
R1027  10K  [0402]  4.61 18.44 90 top
R1028  0E  [0402]  11.57 13.31 180 top
R1029  0E  [0402]  11.57 12.2 180 top
R1031  100mE  [RC0805]  35.9 7.55 270 top
R1032  0E  [0402]  2.27 3.1 90 top
R1033  0E  [0402]  3.4 3.08 90 top
R1034  0E  [0402]  26.24 50.31 0 top
R1035  0E  [0402]  26.24 52.32 0 top
R1036  4.7K  [0402]  26.25 51.38 180 top
R1037  4.7K  [0402]  26.26 49.33 180 top
R1040  20mE  [RC0805]  32.11 3.13 270 top
R1041  20mE  [RC0805]  19.97 7.91 180 top
R1042  0E  [0402]  7.52 35.44 90 bottom
R1043  0E  [0402]  6.43 35.47 90 bottom
R1044  0E  [0402]  8.42 40.07 90 bottom
R1045  0E  [0402]  9.7 40.02 90 bottom
R1059  0E  [0201]  23.45 20.71 180 bottom
R1064  100K  [0201]  30.44 20.58 180 bottom
R1065  0E  [0402]  32.42 19.72 270 bottom
R1066  0E  [0402]  32.42 18.96 90 bottom
R1069  0E  [0402]  23.2 17.61 0 bottom
R1070  0E  [0402]  23.93 17.61 180 bottom
R1083  0E  [0201]  29.22 20.38 0 bottom
R1084  0E  [0402]  23.15 19.21 0 bottom
R1085  0E  [0402]  23.88 19.21 180 bottom
R1087  200K  [0402]  25.76 9.53 0 top
R1088  100K  [0402]  26.4 8.52 0 top
R1089  6.8K  [0201]  9.91 16.8 270 top
R1090  3.3K  [0201]  10.42 19.72 90 top
R1091  0E  [0402]  33.53 14.89 0 bottom
R1092  0E  [0402]  33.53 13.85 0 bottom
R1093  0E  [0402]  24.36 12.2 270 bottom
R1094  0E  [0201]  32.47 21.85 180 bottom
R1095  10K  [0402]  26.24 7.37 180 bottom
R1096  100K  [0201]  24.29 21.37 270 bottom
R1097  100K  [0201]  25.02 21.37 270 bottom
R1098  0E  [0402]  23.88 7.37 180 bottom
R1099  10K  [0402]  33.53 12.86 0 bottom
R1100  10K  [0402]  29.47 21.42 90 bottom
R1102  10K  [0402]  33.53 11.84 180 bottom
R1103  215K  [0402]  61.88 8.06 180 top
R1104  121K  [0402]  63.4 8.16 270 top
TP201  SMD  [TP20_SMD]  43.37 40.2 0 top
TP202  SMD  [TP20_SMD]  41.45 47.91 0 top
TP204  SMD  [TP20_SMD]  39.6 43.12 0 top
TP205  SMD  [TP20_SMD]  43.09 39.65 0 top
TP206  SMD  [TP20_SMD]  43.49 37.93 0 top
TP207  SMD  [TP20_SMD]  43.21 41.22 0 top
TP208  SMD  [TP20_SMD]  43.41 41.79 0 top
TP209  SMD  [TP20_SMD]  43.16 38.5 0 top
TP210  SMD  [TP20_SMD]  43.37 34.69 0 top
TP211  SMD  [TP20_SMD]  43.16 36.39 0 top
TP212  SMD  [TP20_SMD]  43.49 36.96 0 top
TP213  SMD  [TP20_SMD]  43.09 35.24 0 top
TP214  SMD  [TP20_SMD]  43.21 33.68 0 top
TP215  SMD  [TP20_SMD]  43.41 33.11 0 top
TP216  SMD  [TP20_SMD]  39.6 31.78 0 top
TP401  SMD  [TP20_SMD]  59.12 52.44 0 top
TP402  SMD  [TP20_SMD]  48.77 9.2 0 top
TP403  SMD  [TP20_SMD]  48.77 10.17 0 top
TP404  SMD  [TP20_SMD]  48.77 11.23 0 top
TP405  SMD  [TP20_SMD]  48.77 12.2 0 top
TP407  SMD  [TP20_SMD]  57.48 50.14 0 top
TP408  SMD  [TP20_SMD]  56.38 53.12 90 top
TP409  SMD  [TP20_SMD]  58.88 51.31 0 top
TP410  SMD  [TP20_SMD]  56.86 51.99 0 top
TP411  SMD  [TP20_SMD]  56.66 57.47 0 top
TP412  SMD  [TP20_SMD]  64.55 50.63 0 top
TP413  SMD  [TP20_SMD]  56.67 58.57 0 top
TP414  SMD  [TP20_SMD]  57.82 58.54 0 top
TP415  SMD  [TP20_SMD]  58.99 58.57 0 top
TP416  SMD  [TP20_SMD]  60.16 58.55 0 top
TP417  SMD  [TP20_SMD]  67.15 49.31 0 top
TP418  SMD  [TP20_SMD]  57.92 51.29 0 top
TP419  SMD  [TP20_SMD]  58.52 50.22 0 top
TP501  SMD  [TP20_SMD]  59.7 26.06 0 top
TP502  SMD  [TP20_SMD]  54.22 26.25 0 top
TP503  SMD  [TP20_SMD]  53.02 26.25 0 top
TP504  SMD  [TP20_SMD]  55.04 25.79 0 top
TP505  SMD  [TP20_SMD]  56.08 26.27 0 top
TP603  SMD  [TP35_SMD]  69.29 41.59 0 top
TP604  SMD  [TP35_SMD]  71.61 40.94 0 top
TP607  SMD  [TP35_SMD]  45.24 2.01 0 top
TP608  SMD  [TP35_SMD]  61.64 42.66 180 top
TP609  SMD  [TP35_SMD]  51.41 57.21 0 top
TP610  SMD  [TP35_SMD]  62.73 42.66 180 top
TP611  SMD  [TP35_SMD]  52.68 57.21 0 top
TP612  SMD  [TP35_SMD]  63.82 42.66 0 top
TP613  SMD  [TP35_SMD]  53.95 57.21 0 top
TP614  SMD  [TP35_SMD]  64.91 42.66 180 top
TP615  SMD  [TP35_SMD]  55.22 57.21 0 top
TP616  SMD  [TP35_SMD]  66 42.66 0 top
TP617  SMD  [TP35_SMD]  67.1 42.66 0 top
TP703  SMD  [TP35_SMD]  37.17 18.09 0 top
TP706  SMD  [TP35_SMD]  28.71 10.09 0 top
TP707  SMD  [TP35_SMD]  22.36 8.44 0 top
TP708  SMD  [TP35_SMD]  24.92 25.9 0 top
TP709  SMD  [TP35_SMD]  17.71 18.22 0 top
TP711  SMD  [TP35_SMD]  14.69 2.17 0 top
TP712  SMD  [TP35_SMD]  21.6 19.87 0 top
TP713  SMD  [TP35_SMD]  32.52 21.85 0 top
TP801  SMD  [TP50_SMD]  14.18 58.58 0 top
TP802  SMD  [TP50_SMD]  39.65 58.89 0 top
TP803  SMD  [TP50_SMD]  11.31 21.72 0 top
TP804  SMD  [TP50_SMD]  69.93 9.28 0 top
TP805  SMD  [TP35_SMD]  48.77 56.03 0 top
TP901  SMD  [TP35_SMD]  66.63 6.87 0 top
TP902  SMD  [TP35_SMD]  32.59 58.89 270 top
TP903  SMD  [TP35_SMD]  56.19 7.99 0 top
TP904  SMD  [TP35_SMD]  37.37 58.89 270 top
TP905  SMD  [TP35_SMD]  34.98 58.89 270 top
TP906  SMD  [TP35_SMD]  38.22 53.81 270 top
TP907  SMD  [TP35_SMD]  38.17 55.96 270 top
TP908  SMD  [TP35_SMD]  5.78 3.87 90 top
TP909  SMD  [TP35_SMD]  21.87 46.32 0 top
TP910  SMD  [TP35_SMD]  23.81 46.31 90 top
TP911  SMD  [TP35_SMD]  25.27 46.32 0 top
TP915  SMD  [TP35_SMD]  27.59 9.28 0 top
TP917  SMD  [TP35_SMD]  28.1 50.31 0 top
TP918  SMD  [TP35_SMD]  28.28 52.68 0 top
TP919  SMD  [TP35_SMD]  42.86 5.32 0 top
TP920  SMD  [TP35_SMD]  42.85 10.56 0 top
TP921  SMD  [TP35_SMD]  37.7 6.76 0 top
TP922  SMD  [TP35_SMD]  20.07 17.79 0 top
TP923  SMD  [TP35_SMD]  14.86 13.09 0 top
TP924  SMD  [TP35_SMD]  19.79 14.46 0 top
TP925  SMD  [TP35_SMD]  38.33 17.2 0 top
TP926  SMD  [TP35_SMD]  44.48 22.18 0 top
TP927  SMD  [TP35_SMD]  38.44 23.04 0 top
TP928  SMD  [TP35_SMD]  22.18 25.9 0 top
TP929  SMD  [TP35_SMD]  15.93 31.91 0 top
TP930  SMD  [TP35_SMD]  21.09 31.15 0 top
TP931  SMD  [TP35_SMD]  33.99 25.48 0 top
TP932  SMD  [TP35_SMD]  38.13 31.09 0 top
TP933  SMD  [TP35_SMD]  33.13 29.98 0 top
TP934  SMD  [TP35_SMD]  28.73 24.29 0 top
TP935  SMD  [TP35_SMD]  22.36 23.12 0 top
TP936  SMD  [TP35_SMD]  21.6 21.27 0 top
TP937  SMD  [TP35_SMD]  17.35 20.15 0 top
TP938  SMD  [TP35_SMD]  7.66 4.25 0 top
TP939  SMD  [TP35_SMD]  8.88 7.46 0 top
TP940  SMD  [TP35_SMD]  36.46 1.72 0 top
TP941  SMD  [TP35_SMD]  36.51 3.99 0 top
TP942  SMD  [TP35_SMD]  17.71 7.91 0 top
TP943  SMD  [TP35_SMD]  13.04 9 0 top
TP944  SMD  [TP35_SMD]  34.09 8.31 0 top
TP945  SMD  [TP35_SMD]  34.22 6.23 0 top
TP946  SMD  [TP35_SMD]  20.07 11.82 0 top
TP947  SMD  [TP35_SMD]  14.97 9.86 0 top
TP948  SMD  [TP35_SMD]  29.75 25.48 0 top
TP949  SMD  [TP35_SMD]  30.83 29.77 0 top
TP950  SMD  [TP35_SMD]  15.52 26.36 0 top
TP951  SMD  [TP35_SMD]  24.49 31.15 0 top
TP952  SMD  [TP35_SMD]  41 4.35 0 top
TP953  SMD  [TP35_SMD]  32.29 46.99 0 top
TP954  SMD  [TP35_SMD]  38.77 47.48 0 top
TP955  SMD  [TP35_SMD]  38.77 50.81 0 top
TP956  SMD  [TP35_SMD]  67.09 24.16 0 top
TP957  SMD  [TP35_SMD]  28.96 1.51 0 top
TP958  SMD  [TP35_SMD]  67.57 20.77 0 top
TP959  SMD  [TP35_SMD]  22.38 4.55 0 top
TP960  SMD  [TP35_SMD]  16.26 7.86 0 top
TP961  SMD  [TP35_SMD]  14.87 45.53 90 top
TP962  SMD  [TP35_SMD]  14.87 47.1 90 top
TP963  SMD  [TP35_SMD]  14.86 49.26 90 top
TP964  SMD  [TP35_SMD]  15.32 51.71 90 top
TP965  SMD  [TP35_SMD]  15.34 53.97 90 top
TP969  SMD  [TP35_SMD]  24.85 21.85 0 top
TP970  SMD  [TP35_SMD]  23.6 21.85 0 top
TP972  SMD  [TP35_SMD]  61.98 27.24 0 top
U101  MIMX9352CVVXMAB  [BGA306_0P5_11X11_CST_A1]  52.72 38.45 90 top
U201  MT53E2G32D4DE-046  [BGA200_0P65_10X14P5_F_A1]  35.18 37.45 270 top
U501  SDINBDA6-16G  [BGA153_0P5_11P5X13_C_A2]  57.76 19.24 270 top
U701  TPS6521905RSM  [VQFN32_0P4_4X4_EP_A1]  27.57 17.47 180 top
U901  DML3006LFDS  [DFN7_0P5_2P05X2P05_EP_A1]  45.73 8.14 90 top
U902  PAC1934T-I/JQ  [UQFN16_0P65_4X4_EP_A1]  6.21 40.47 0 top
U903  TPS22990NDML  [WSON10_0P5_2X3_EP_B_A1]  14.97 15.92 270 top
U904  PAC1934T-I/JQ  [UQFN16_0P65_4X4_EP_A1]  6.11 53.49 0 top
U905  TPS78401DBV  [SOT23-5L_0P95_2P9X1P6_E_A1]  62.46 5.42 0 top
U906  TPS22990NDML  [WSON10_0P5_2X3_EP_B_A1]  44.43 18.24 90 top
U907  PAC1934T-I/JQ  [UQFN16_0P65_4X4_EP_A1]  19.32 40.32 0 top
U908  TPS22990NDML  [WSON10_0P5_2X3_EP_B_A1]  18.85 28.66 90 top
U909  ADP5585ACP  [LFCSP16_0P5_3X3_EP_A_A1]  21.88 51.23 0 top
U910  TPS22990NDML  [WSON10_0P5_2X3_EP_B_A1]  37.52 28.07 90 top
U911  PAC1934T-I/JQ  [UQFN16_0P65_4X4_EP_A1]  6.44 27.51 0 top
U912  PAC1934T-I/JQ  [UQFN16_0P65_4X4_EP_A1]  6.46 14.06 0 top
U913  PCT2075  [SON8_0P5_3X2_EP_A1]  3.09 6.33 90 top
U914  93LC56BT-I/OT  [SOT23-6L_0P95_2P9X1P6_K_A1]  34.07 49.38 270 top
U919  TPS62A02  [SOT563-6L_0P5_1P6X1P2_A_A1]  26.04 6.64 0 top
U920  TLV74018PDQN  [X2SON4_0P65_1X1_EP_A1]  10.93 18.42 180 top
Y401  24MHz  [XTAL4_1P6_3P2X2P5_A_A1]  64.06 48 270 top

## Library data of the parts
BH801-BH804 = MECH_MH_PL
C101 C102 C106-C111 C114 C116-C119 C124 C129-C132 C134-C149 C151-C156 C201-C222 C401-C405 C501-C509 C702 C704 C706-C709 C712-C715 C718-C727 C729-C731 C801-C809 C901-C918 C920-C954 C996 C1013 C1021-C1024 = CAP_NP
D601 = DIODE_LED
D901-D904 = DIODE_SCH
J801 J802 = CONN_B2B_2X40_84P_A_A1
J803 = CONN_B2B_2X50_104P
J901 = CST_CONN_B2B_2X6_16P_A1
L102 = FER_BEAD
L702 = IND_CORE_A
L704-L706 = IND_CORE_POL_B
Q901 = TRANS_NMOS-ENX1_3P_N_A1
Q902 Q903 = TRANS_NMOS-ENX1_3P
QZ401 = CRYSTAL
R101-R113 R201-R211 R301-R312 R401 R403-R406 R411-R418 R501 R502 R601-R605 R609-R614 R702 R703 R706 R707 R712-R715 R717 R719 R724-R727 R801 R802 R901-R924 R926-R939 R941-R953 R955-R985 R987-R1029 R1031-R1037 R1040-R1045 R1059 R1064-R1066 R1069 R1070 R1083-R1085 R1087-R1100 R1102-R1104 = RES
TP201 TP202 TP204-TP216 TP401-TP405 TP407-TP419 TP501-TP505 TP801-TP804 = TEST_POINT_SMD
TP603 TP604 TP607-TP617 TP703 TP706-TP709 TP711-TP713 TP805 TP901-TP911 TP915 TP917-TP965 TP969 TP970 TP972 = TEST_POINT_SMD: User Part Number: USERPART#; Tolerance: TOLERANCE
U101 = CST_IC_MIMX93XX_BGA-306P_A1
U201 = CST_IC_DDR4-SDRAMX32_200P_A1
U501 = CST_IC_NANDFLASH_BGA-153P_A1
U701 = IC_TPS65219_32P_EP_A1
U901 = IC_LOAD_SWITCH_8P_EP_G_A1
U902 U904 U907 U911 U912 = IC_PAC1934_16P_EP_A1
U903 U906 U908 U910 = IC_LOAD_SWITCH_8P_EP_C_A1
U905 = IC_LDO-ADJ_5P_F_A1
U909 = IC_ADP5585_16P_EP_A1
U913 = IC_TEMP-SENSOR_8P_EP_A_A1
U914 = IC_EEPROM-3WIRE_6P_A1
U919 = IC_SWITCHER_6P_Y_A1
U920 = IC_LDO-FIXED_4P_EP_A_A2
Y401 = CRYSTAL_4P

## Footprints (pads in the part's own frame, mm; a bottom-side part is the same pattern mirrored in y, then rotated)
0201
  rect 0.305x0.305 smd: 1(-0.267,0) 2(0.267,0)
0402
  rect 0.457x0.508 smd: 1(-0.375,0) 2(0.375,0)
0603
  rect 0.711x0.838 smd: 1(-0.65,0) 2(0.65,0)
0805
  rect 1.143x1.448 smd: 1(-0.9,0) 2(0.9,0)
1206_T_A1
  rect 1.143x1.803 smd: 1(-1.575,0) 2(1.575,0)
BGA153_0P5_11P5X13_C_A2
  round 0.254 smd: A1(-3.25,3.25) A2(-2.75,3.25) A3(-2.25,3.25) A4(-1.75,3.25) A5(-1.25,3.25) A6(-0.75,3.25) A7(-0.25,3.25) A8(0.25,3.25) A9(0.75,3.25) A10(1.25,3.25) A11(1.75,3.25) A12(2.25,3.25) A13(2.75,3.25) A14(3.25,3.25) B1(-3.25,2.75) B2(-2.75,2.75) B3(-2.25,2.75) B4(-1.75,2.75) B5(-1.25,2.75) B6(-0.75,2.75) B7(-0.25,2.75) B8(0.25,2.75) B9(0.75,2.75) B10(1.25,2.75) B11(1.75,2.75) B12(2.25,2.75) B13(2.75,2.75) B14(3.25,2.75) C1(-3.25,2.25) C2(-2.75,2.25) C3(-2.25,2.25) C4(-1.75,2.25) C5(-1.25,2.25) C6(-0.75,2.25) C7(-0.25,2.25) C8(0.25,2.25) C9(0.75,2.25) C10(1.25,2.25) C11(1.75,2.25) C12(2.25,2.25) C13(2.75,2.25) C14(3.25,2.25) D1(-3.25,1.75) D2(-2.75,1.75) D3(-2.25,1.75) D4(-1.75,1.75) D12(2.25,1.75) D13(2.75,1.75) D14(3.25,1.75) E1(-3.25,1.25) E2(-2.75,1.25) E3(-2.25,1.25) E5(-1.25,1.25) E6(-0.75,1.25) E7(-0.25,1.25) E8(0.25,1.25) E9(0.75,1.25) E10(1.25,1.25) E12(2.25,1.25) E13(2.75,1.25) E14(3.25,1.25) F1(-3.25,0.75) F2(-2.75,0.75) F3(-2.25,0.75) F5(-1.25,0.75) F10(1.25,0.75) F12(2.25,0.75) F13(2.75,0.75) F14(3.25,0.75) G1(-3.25,0.25) G2(-2.75,0.25) G3(-2.25,0.25) G5(-1.25,0.25) G10(1.25,0.25) G12(2.25,0.25) G13(2.75,0.25) G14(3.25,0.25) H1(-3.25,-0.25) H2(-2.75,-0.25) H3(-2.25,-0.25) H5(-1.25,-0.25) H10(1.25,-0.25) H12(2.25,-0.25) H13(2.75,-0.25) H14(3.25,-0.25) J1(-3.25,-0.75) J2(-2.75,-0.75) J3(-2.25,-0.75) J5(-1.25,-0.75) J10(1.25,-0.75) J12(2.25,-0.75) J13(2.75,-0.75) J14(3.25,-0.75) K1(-3.25,-1.25) K2(-2.75,-1.25) K3(-2.25,-1.25) K5(-1.25,-1.25) K6(-0.75,-1.25) K7(-0.25,-1.25) K8(0.25,-1.25) K9(0.75,-1.25) K10(1.25,-1.25) K12(2.25,-1.25) K13(2.75,-1.25) K14(3.25,-1.25) L1(-3.25,-1.75) L2(-2.75,-1.75) L3(-2.25,-1.75) L12(2.25,-1.75) L13(2.75,-1.75) L14(3.25,-1.75) M1(-3.25,-2.25) M2(-2.75,-2.25) M3(-2.25,-2.25) M4(-1.75,-2.25) M5(-1.25,-2.25) M6(-0.75,-2.25) M7(-0.25,-2.25) M8(0.25,-2.25) M9(0.75,-2.25) M10(1.25,-2.25) M11(1.75,-2.25) M12(2.25,-2.25) M13(2.75,-2.25) M14(3.25,-2.25) N1(-3.25,-2.75) N2(-2.75,-2.75) N3(-2.25,-2.75) N4(-1.75,-2.75) N5(-1.25,-2.75) N6(-0.75,-2.75) N7(-0.25,-2.75) N8(0.25,-2.75) N9(0.75,-2.75) N10(1.25,-2.75) N11(1.75,-2.75) N12(2.25,-2.75) N13(2.75,-2.75) N14(3.25,-2.75) P1(-3.25,-3.25) P2(-2.75,-3.25) P3(-2.25,-3.25) P4(-1.75,-3.25) P5(-1.25,-3.25) P6(-0.75,-3.25) P7(-0.25,-3.25) P8(0.25,-3.25) P9(0.75,-3.25) P10(1.25,-3.25) P11(1.75,-3.25) P12(2.25,-3.25) P13(2.75,-3.25) P14(3.25,-3.25)
BGA200_0P65_10X14P5_F_A1
  round 0.356 smd: A1(-4.4,6.825) A2(-3.6,6.825) A3(-2.8,6.825) A4(-2,6.825) A5(-1.2,6.825) A8(1.2,6.825) A9(2,6.825) A10(2.8,6.825) A11(3.6,6.825) A12(4.4,6.825) AA1(-4.4,-6.175) AA2(-3.6,-6.175) AA3(-2.8,-6.175) AA4(-2,-6.175) AA5(-1.2,-6.175) AA8(1.2,-6.175) AA9(2,-6.175) AA10(2.8,-6.175) AA11(3.6,-6.175) AA12(4.4,-6.175) AB1(-4.4,-6.825) AB2(-3.6,-6.825) AB3(-2.8,-6.825) AB4(-2,-6.825) AB5(-1.2,-6.825) AB8(1.2,-6.825) AB9(2,-6.825) AB10(2.8,-6.825) AB11(3.6,-6.825) AB12(4.4,-6.825) B1(-4.4,6.175) B2(-3.6,6.175) B3(-2.8,6.175) B4(-2,6.175) B5(-1.2,6.175) B8(1.2,6.175) B9(2,6.175) B10(2.8,6.175) B11(3.6,6.175) B12(4.4,6.175) C1(-4.4,5.525) C2(-3.6,5.525) C3(-2.8,5.525) C4(-2,5.525) C5(-1.2,5.525) C8(1.2,5.525) C9(2,5.525) C10(2.8,5.525) C11(3.6,5.525) C12(4.4,5.525) D1(-4.4,4.875) D2(-3.6,4.875) D3(-2.8,4.875) D4(-2,4.875) D5(-1.2,4.875) D8(1.2,4.875) D9(2,4.875) D10(2.8,4.875) D11(3.6,4.875) D12(4.4,4.875) E1(-4.4,4.225) E2(-3.6,4.225) E3(-2.8,4.225) E4(-2,4.225) E5(-1.2,4.225) E8(1.2,4.225) E9(2,4.225) E10(2.8,4.225) E11(3.6,4.225) E12(4.4,4.225) F1(-4.4,3.575) F2(-3.6,3.575) F3(-2.8,3.575) F4(-2,3.575) F5(-1.2,3.575) F8(1.2,3.575) F9(2,3.575) F10(2.8,3.575) F11(3.6,3.575) F12(4.4,3.575) G1(-4.4,2.925) G2(-3.6,2.925) G3(-2.8,2.925) G4(-2,2.925) G5(-1.2,2.925) G8(1.2,2.925) G9(2,2.925) G10(2.8,2.925) G11(3.6,2.925) G12(4.4,2.925) H1(-4.4,2.275) H2(-3.6,2.275) H3(-2.8,2.275) H4(-2,2.275) H5(-1.2,2.275) H8(1.2,2.275) H9(2,2.275) H10(2.8,2.275) H11(3.6,2.275) H12(4.4,2.275) J1(-4.4,1.625) J2(-3.6,1.625) J3(-2.8,1.625) J4(-2,1.625) J5(-1.2,1.625) J8(1.2,1.625) J9(2,1.625) J10(2.8,1.625) J11(3.6,1.625) J12(4.4,1.625) K1(-4.4,0.975) K2(-3.6,0.975) K3(-2.8,0.975) K4(-2,0.975) K5(-1.2,0.975) K8(1.2,0.975) K9(2,0.975) K10(2.8,0.975) K11(3.6,0.975) K12(4.4,0.975) N1(-4.4,-0.975) N2(-3.6,-0.975) N3(-2.8,-0.975) N4(-2,-0.975) N5(-1.2,-0.975) N8(1.2,-0.975) N9(2,-0.975) N10(2.8,-0.975) N11(3.6,-0.975) N12(4.4,-0.975) P1(-4.4,-1.625) P2(-3.6,-1.625) P3(-2.8,-1.625) P4(-2,-1.625) P5(-1.2,-1.625) P8(1.2,-1.625) P9(2,-1.625) P10(2.8,-1.625) P11(3.6,-1.625) P12(4.4,-1.625) R1(-4.4,-2.275) R2(-3.6,-2.275) R3(-2.8,-2.275) R4(-2,-2.275) R5(-1.2,-2.275) R8(1.2,-2.275) R9(2,-2.275) R10(2.8,-2.275) R11(3.6,-2.275) R12(4.4,-2.275) T1(-4.4,-2.925) T2(-3.6,-2.925) T3(-2.8,-2.925) T4(-2,-2.925) T5(-1.2,-2.925) T8(1.2,-2.925) T9(2,-2.925) T10(2.8,-2.925) T11(3.6,-2.925) T12(4.4,-2.925) U1(-4.4,-3.575) U2(-3.6,-3.575) U3(-2.8,-3.575) U4(-2,-3.575) U5(-1.2,-3.575) U8(1.2,-3.575) U9(2,-3.575) U10(2.8,-3.575) U11(3.6,-3.575) U12(4.4,-3.575) V1(-4.4,-4.225) V2(-3.6,-4.225) V3(-2.8,-4.225) V4(-2,-4.225) V5(-1.2,-4.225) V8(1.2,-4.225) V9(2,-4.225) V10(2.8,-4.225) V11(3.6,-4.225) V12(4.4,-4.225) W1(-4.4,-4.875) W2(-3.6,-4.875) W3(-2.8,-4.875) W4(-2,-4.875) W5(-1.2,-4.875) W8(1.2,-4.875) W9(2,-4.875) W10(2.8,-4.875) W11(3.6,-4.875) W12(4.4,-4.875) Y1(-4.4,-5.525) Y2(-3.6,-5.525) Y3(-2.8,-5.525) Y4(-2,-5.525) Y5(-1.2,-5.525) Y8(1.2,-5.525) Y9(2,-5.525) Y10(2.8,-5.525) Y11(3.6,-5.525) Y12(4.4,-5.525)
BGA306_0P5_11X11_CST_A1
  round 0 hole 1.699 unplated: (-6.863,6.863) (-6.863,-6.863) (6.863,6.863) (6.863,-6.863)
  round 0 hole 0.848 unplated: (-6.863,-1.783) (6.863,4.323)
  round 0.254 smd: A1(5.25,5) A2(5.25,4.5) A3(5.25,4) A4(5.25,3.5) A5(5.25,3) A6(5.25,2.5) A7(5.25,2) A8(5.25,1.5) A9(5.25,1) A10(5.25,0.5) A11(5.25,0) A12(5.25,-0.5) A13(5.25,-1) A14(5.25,-1.5) A15(5.25,-2) A16(5.25,-2.5) A17(5.25,-3) A18(5.25,-3.5) A19(5.25,-4) A20(5.25,-4.5) A21(5.25,-5) AA1(-4.75,5) AA2(-4.75,4.5) AA3(-4.75,4) AA4(-4.75,3.5) AA5(-4.75,3) AA6(-4.75,2.5) AA7(-4.75,2) AA8(-4.75,1.5) AA9(-4.75,1) AA10(-4.75,0.5) AA11(-4.75,0) AA12(-4.75,-0.5) AA13(-4.75,-1) AA14(-4.75,-1.5) AA15(-4.75,-2) AA16(-4.75,-2.5) AA17(-4.75,-3) AA18(-4.75,-3.5) AA19(-4.75,-4) AA20(-4.75,-4.5) AA21(-4.75,-5) B1(4.75,5) B2(4.75,4.5) B3(4.75,4) B4(4.75,3.5) B5(4.75,3) B6(4.75,2.5) B7(4.75,2) B8(4.75,1.5) B9(4.75,1) B10(4.75,0.5) B11(4.75,0) B12(4.75,-0.5) B13(4.75,-1) B14(4.75,-1.5) B15(4.75,-2) B16(4.75,-2.5) B17(4.75,-3) B18(4.75,-3.5) B19(4.75,-4) B20(4.75,-4.5) B21(4.75,-5) C1(4.25,5) C2(4.25,4.5) C4(4.25,3.5) C6(4.25,2.5) C8(4.25,1.5) C10(4.25,0.5) C11(4.25,0) C12(4.25,-0.5) C14(4.25,-1.5) C16(4.25,-2.5) C18(4.25,-3.5) C20(4.25,-4.5) C21(4.25,-5) D1(3.75,5) D2(3.75,4.5) D4(3.75,3.5) D6(3.75,2.5) D8(3.75,1.5) D10(3.75,0.5) D12(3.75,-0.5) D14(3.75,-1.5) D16(3.75,-2.5) D18(3.75,-3.5) D20(3.75,-4.5) D21(3.75,-5) E1(3.25,5) E2(3.25,4.5) E3(3.25,4) E4(3.25,3.5) E6(3.25,2.5) E8(3.25,1.5) E10(3.25,0.5) E12(3.25,-0.5) E14(3.25,-1.5) E16(3.25,-2.5) E18(3.25,-3.5) E19(3.25,-4) E20(3.25,-4.5) E21(3.25,-5) F1(2.75,5) F2(2.75,4.5) F6(2.75,2.5) F8(2.75,1.5) F10(2.75,0.5) F12(2.75,-0.5) F14(2.75,-1.5) F16(2.75,-2.5) F20(2.75,-4.5) F21(2.75,-5) G1(2.25,5) G2(2.25,4.5) G3(2.25,4) G4(2.25,3.5) G5(2.25,3) G6(2.25,2.5) G8(2.25,1.5) G10(2.25,0.5) G12(2.25,-0.5) G14(2.25,-1.5) G16(2.25,-2.5) G17(2.25,-3) G18(2.25,-3.5) G19(2.25,-4) G20(2.25,-4.5) G21(2.25,-5) H1(1.75,5) H2(1.75,4.5) H8(1.75,1.5) H10(1.75,0.5) H12(1.75,-0.5) H14(1.75,-1.5) H20(1.75,-4.5) H21(1.75,-5) J1(1.25,5) J2(1.25,4.5) J3(1.25,4) J4(1.25,3.5) J5(1.25,3) J6(1.25,2.5) J7(1.25,2) J8(1.25,1.5) J9(1.25,1) J10(1.25,0.5) J11(1.25,0) J12(1.25,-0.5) J13(1.25,-1) J14(1.25,-1.5) J15(1.25,-2) J16(1.25,-2.5) J17(1.25,-3) J18(1.25,-3.5) J19(1.25,-4) J20(1.25,-4.5) J21(1.25,-5) K1(0.75,5) K2(0.75,4.5) K9(0.75,1) K10(0.75,0.5) K11(0.75,0) K12(0.75,-0.5) K13(0.75,-1) K20(0.75,-4.5) K21(0.75,-5) L1(0.25,5) L2(0.25,4.5) L3(0.25,4) L4(0.25,3.5) L5(0.25,3) L6(0.25,2.5) L7(0.25,2) L8(0.25,1.5) L14(0.25,-1.5) L15(0.25,-2) L16(0.25,-2.5) L17(0.25,-3) L18(0.25,-3.5) L19(0.25,-4) L20(0.25,-4.5) L21(0.25,-5) M1(-0.25,5) M2(-0.25,4.5) M9(-0.25,1) M10(-0.25,0.5) M11(-0.25,0) M12(-0.25,-0.5) M13(-0.25,-1) M20(-0.25,-4.5) M21(-0.25,-5) N1(-0.75,5) N2(-0.75,4.5) N3(-0.75,4) N4(-0.75,3.5) N5(-0.75,3) N6(-0.75,2.5) N7(-0.75,2) N8(-0.75,1.5) N9(-0.75,1) N10(-0.75,0.5) N11(-0.75,0) N12(-0.75,-0.5) N13(-0.75,-1) N14(-0.75,-1.5) N15(-0.75,-2) N16(-0.75,-2.5) N17(-0.75,-3) N18(-0.75,-3.5) N19(-0.75,-4) N20(-0.75,-4.5) N21(-0.75,-5) P1(-1.25,5) P2(-1.25,4.5) P8(-1.25,1.5) P10(-1.25,0.5) P12(-1.25,-0.5) P14(-1.25,-1.5) P20(-1.25,-4.5) P21(-1.25,-5) R1(-1.75,5) R2(-1.75,4.5) R3(-1.75,4) R4(-1.75,3.5) R5(-1.75,3) R6(-1.75,2.5) R8(-1.75,1.5) R10(-1.75,0.5) R12(-1.75,-0.5) R14(-1.75,-1.5) R16(-1.75,-2.5) R17(-1.75,-3) R18(-1.75,-3.5) R19(-1.75,-4) R20(-1.75,-4.5) R21(-1.75,-5) T1(-2.25,5) T2(-2.25,4.5) T6(-2.25,2.5) T8(-2.25,1.5) T10(-2.25,0.5) T12(-2.25,-0.5) T14(-2.25,-1.5) T16(-2.25,-2.5) T20(-2.25,-4.5) T21(-2.25,-5) U1(-2.75,5) U2(-2.75,4.5) U3(-2.75,4) U4(-2.75,3.5) U6(-2.75,2.5) U8(-2.75,1.5) U10(-2.75,0.5) U12(-2.75,-0.5) U14(-2.75,-1.5) U16(-2.75,-2.5) U18(-2.75,-3.5) U19(-2.75,-4) U20(-2.75,-4.5) U21(-2.75,-5) V1(-3.25,5) V2(-3.25,4.5) V4(-3.25,3.5) V6(-3.25,2.5) V8(-3.25,1.5) V10(-3.25,0.5) V12(-3.25,-0.5) V14(-3.25,-1.5) V16(-3.25,-2.5) V18(-3.25,-3.5) V20(-3.25,-4.5) V21(-3.25,-5) W1(-3.75,5) W2(-3.75,4.5) W4(-3.75,3.5) W6(-3.75,2.5) W8(-3.75,1.5) W10(-3.75,0.5) W11(-3.75,0) W12(-3.75,-0.5) W14(-3.75,-1.5) W16(-3.75,-2.5) W18(-3.75,-3.5) W20(-3.75,-4.5) W21(-3.75,-5) Y1(-4.25,5) Y2(-4.25,4.5) Y3(-4.25,4) Y4(-4.25,3.5) Y5(-4.25,3) Y6(-4.25,2.5) Y7(-4.25,2) Y8(-4.25,1.5) Y9(-4.25,1) Y10(-4.25,0.5) Y11(-4.25,0) Y12(-4.25,-0.5) Y13(-4.25,-1) Y14(-4.25,-1.5) Y15(-4.25,-2) Y16(-4.25,-2.5) Y17(-4.25,-3) Y18(-4.25,-3.5) Y19(-4.25,-4) Y20(-4.25,-4.5) Y21(-4.25,-5)
CON_B2B_2X6M_0P4_SM_ST_A2
  rect 0.229x0.66 smd: 1(-1,1.355) 2(-1,-1.355) 3(-0.6,1.355) 4(-0.6,-1.355) 5(-0.2,1.355) 6(-0.2,-1.355) 7(0.2,1.355) 8(0.2,-1.355) 9(0.6,1.355) 10(0.6,-1.355) 11(1,1.355) 12(1,-1.355)
  rect 0.356x0.66 smd: M1(-1.475,1.355) M2(-1.475,-1.355) M3(1.475,1.355) M4(1.475,-1.355)
CON_B2B_2X40M_0P4_SM_ST_D_A1
  rect 0.203x0.686 smd: 1(7.8,-1.368) 2(7.8,1.368) 3(7.4,-1.368) 4(7.4,1.368) 5(7,-1.368) 6(7,1.368) 7(6.6,-1.368) 8(6.6,1.368) 9(6.2,-1.368) 10(6.2,1.368) 11(5.8,-1.368) 12(5.8,1.368) 13(5.4,-1.368) 14(5.4,1.368) 15(5,-1.368) 16(5,1.368) 17(4.6,-1.368) 18(4.6,1.368) 19(4.2,-1.368) 20(4.2,1.368) 21(3.8,-1.368) 22(3.8,1.368) 23(3.4,-1.368) 24(3.4,1.368) 25(3,-1.368) 26(3,1.368) 27(2.6,-1.368) 28(2.6,1.368) 29(2.2,-1.368) 30(2.2,1.368) 31(1.8,-1.368) 32(1.8,1.368) 33(1.4,-1.368) 34(1.4,1.368) 35(1,-1.368) 36(1,1.368) 37(0.6,-1.368) 38(0.6,1.368) 39(0.2,-1.368) 40(0.2,1.368) 41(-0.2,-1.368) 42(-0.2,1.368) 43(-0.6,-1.368) 44(-0.6,1.368) 45(-1,-1.368) 46(-1,1.368) 47(-1.4,-1.368) 48(-1.4,1.368) 49(-1.8,-1.368) 50(-1.8,1.368) 51(-2.2,-1.368) 52(-2.2,1.368) 53(-2.6,-1.368) 54(-2.6,1.368) 55(-3,-1.368) 56(-3,1.368) 57(-3.4,-1.368) 58(-3.4,1.368) 59(-3.8,-1.368) 60(-3.8,1.368) 61(-4.2,-1.368) 62(-4.2,1.368) 63(-4.6,-1.368) 64(-4.6,1.368) 65(-5,-1.368) 66(-5,1.368) 67(-5.4,-1.368) 68(-5.4,1.368) 69(-5.8,-1.368) 70(-5.8,1.368) 71(-6.2,-1.368) 72(-6.2,1.368) 73(-6.6,-1.368) 74(-6.6,1.368) 75(-7,-1.368) 76(-7,1.368) 77(-7.4,-1.368) 78(-7.4,1.368) 79(-7.8,-1.368) 80(-7.8,1.368)
  rect 0.356x0.686 smd: M1(8.275,-1.368) M2(8.275,1.368) M3(-8.275,-1.368) M4(-8.275,1.368)
CON_B2B_2X50M_0P4_SM_ST_A_A2
  rect 0.229x0.66 smd: 1(-9.8,1.355) 2(-9.8,-1.355) 3(-9.4,1.355) 4(-9.4,-1.355) 5(-9,1.355) 6(-9,-1.355) 7(-8.6,1.355) 8(-8.6,-1.355) 9(-8.2,1.355) 10(-8.2,-1.355) 11(-7.8,1.355) 12(-7.8,-1.355) 13(-7.4,1.355) 14(-7.4,-1.355) 15(-7,1.355) 16(-7,-1.355) 17(-6.6,1.355) 18(-6.6,-1.355) 19(-6.2,1.355) 20(-6.2,-1.355) 21(-5.8,1.355) 22(-5.8,-1.355) 23(-5.4,1.355) 24(-5.4,-1.355) 25(-5,1.355) 26(-5,-1.355) 27(-4.6,1.355) 28(-4.6,-1.355) 29(-4.2,1.355) 30(-4.2,-1.355) 31(-3.8,1.355) 32(-3.8,-1.355) 33(-3.4,1.355) 34(-3.4,-1.355) 35(-3,1.355) 36(-3,-1.355) 37(-2.6,1.355) 38(-2.6,-1.355) 39(-2.2,1.355) 40(-2.2,-1.355) 41(-1.8,1.355) 42(-1.8,-1.355) 43(-1.4,1.355) 44(-1.4,-1.355) 45(-1,1.355) 46(-1,-1.355) 47(-0.6,1.355) 48(-0.6,-1.355) 49(-0.2,1.355) 50(-0.2,-1.355) 51(0.2,1.355) 52(0.2,-1.355) 53(0.6,1.355) 54(0.6,-1.355) 55(1,1.355) 56(1,-1.355) 57(1.4,1.355) 58(1.4,-1.355) 59(1.8,1.355) 60(1.8,-1.355) 61(2.2,1.355) 62(2.2,-1.355) 63(2.6,1.355) 64(2.6,-1.355) 65(3,1.355) 66(3,-1.355) 67(3.4,1.355) 68(3.4,-1.355) 69(3.8,1.355) 70(3.8,-1.355) 71(4.2,1.355) 72(4.2,-1.355) 73(4.6,1.355) 74(4.6,-1.355) 75(5,1.355) 76(5,-1.355) 77(5.4,1.355) 78(5.4,-1.355) 79(5.8,1.355) 80(5.8,-1.355) 81(6.2,1.355) 82(6.2,-1.355) 83(6.6,1.355) 84(6.6,-1.355) 85(7,1.355) 86(7,-1.355) 87(7.4,1.355) 88(7.4,-1.355) 89(7.8,1.355) 90(7.8,-1.355) 91(8.2,1.355) 92(8.2,-1.355) 93(8.6,1.355) 94(8.6,-1.355) 95(9,1.355) 96(9,-1.355) 97(9.4,1.355) 98(9.4,-1.355) 99(9.8,1.355) 100(9.8,-1.355)
  rect 0.356x0.66 smd: S1(-10.275,1.355) S2(-10.275,-1.355) S3(10.275,1.355) S4(10.275,-1.355)
DFN7_0P5_2P05X2P05_EP_A1
  rect 0.483x0.33 smd: 1(-0.91,0.75) 2(-0.91,0.25) 3(-0.91,-0.25) 4(-0.91,-0.75) 5(0.91,-0.75) 6(0.91,-0.25)
  custom 0.12x0.12 smd: 7(0.911,0.5)
  rect 1.016x1.651 smd: 9(0,0)
DIO_SOD323F_B_A1
  rect 0.889x1.219 smd: 1(0,1.27) 2(0,-1.27)
FBEAD-0603_A_A1
  rect 0.991x0.813 smd: 1(-0.69,0) 2(0.69,0)
IND2_1P8_2X1P2_POL_A1
  rect 0.61x1.194 smd: 1(-0.9,0) 2(0.9,0)
IND2_1P8_3P2X3P5_A_A1
  rect 0.813x3.2 smd: 1(-0.9,0) 2(0.9,0)
IND2_3_3P5X3P2_B_A1
  rect 1.092x1.448 smd: 1(-1.5,0) 2(1.5,0)
LED-0603_L_A1
  rect 1.016x1.016 smd: 1(-0.762,0) 2(0.762,0)
LFCSP16_0P5_3X3_EP_A_A1
  oval 0.813x0.279 smd: 1(-1.506,0.75) 2(-1.506,0.25) 3(-1.506,-0.25) 4(-1.506,-0.75) 9(1.506,-0.75) 10(1.506,-0.25) 11(1.506,0.25) 12(1.506,0.75)
  oval 0.279x0.813 smd: 5(-0.75,-1.506) 6(-0.25,-1.506) 7(0.25,-1.506) 8(0.75,-1.506) 13(0.75,1.506) 14(0.25,1.506) 15(-0.25,1.506) 16(-0.75,1.506)
  rect 1.702x1.702 smd: 17(0,0)
